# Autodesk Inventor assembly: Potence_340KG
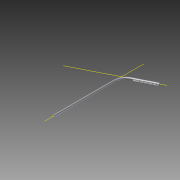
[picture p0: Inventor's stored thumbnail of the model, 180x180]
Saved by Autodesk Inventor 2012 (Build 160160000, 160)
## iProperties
Created: 2016-01
Part Number: Potence_340KG
Document SubType Name: Assembly
Designer: wmfoihay
Author: wmfoihay
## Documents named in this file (3)
- G:\BU_Transport\DIPS\BE\MFOIHAYA\Projet Potence\INVENTOR\Potence 340 kg.iam
- G:\BU_Transport\DIPS\BE\MFOIHAYA\Projet Potence\INVENTOR\MAT 340kg.ipt
- G:\BU_Transport\DIPS\BE\MFOIHAYA\Projet Potence\INVENTOR\PLAT.ipt
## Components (2 placed, 2 different names)
1. Mat:1 — Logement:1, Angle:1
2. Plat:1 — Logement:1, Angle:1, Placage:1, Placage:2
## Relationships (4: Mate 2, Insert 1, Angle 1)
- Logement:1 [Insert]: Mat:1 ↔ Plat:1
- Angle:1: Mat:1 ↔ Plat:1
- Placage:1 [Mate]: Plat:1
- Placage:2 [Mate]: Plat:1
